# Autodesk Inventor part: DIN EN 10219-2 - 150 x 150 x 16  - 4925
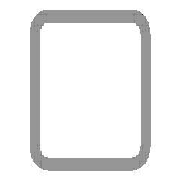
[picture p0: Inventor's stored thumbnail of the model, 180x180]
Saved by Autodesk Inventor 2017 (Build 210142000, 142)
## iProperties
IsCustomPart: 1
Created: 2017-11
Part Number: DIN EN 10219-2 - 150 x 150 x 16  - 4925
Material: Steel, Mild
Description: Cold formed welded structural hollow sections of non-alloy and fine grain structural steel
Document SubType Name: Modeling
Standard: DIN
Designer: iusti
Standard Revision: 2006-07
Standards Organization: DIN
Language: en-US
Size Designation: 150 x 150 x 16
Categories: <MemberInstance><Categories><Category DisplayName="Structural Shapes" InternalName="089c4875-fa83-4c05-b084-43b9cc11f5ed" Mnemonic="GRDR"><CategoryParameter Dis
Stock Number: 150 x 150 x 16
Density: 7.85 g/cm^3
Appearance: Semi-Polished
Mass: 289079 g
Surface Area: 46181.3 cm^2
Volume: 36825.4 cm^3
_CCFamilyMember: 76
_CCFamilyDisplayName: DIN EN 10219-2 (Square Hollow Section - Cold Formed) - Cold formed welded structural hollow sections of non-alloy and fine grain structural steel
_FrameMemberDoc: Frame Member File
_Version: 15.0.0
_GetPNFromCC: 1
G_L: 4925.000 mm
G_W: 150.000 mm
G_H: 150.000 mm
+3C696B27-B370-4381-981B-8782BFEB3638+CUTDETAIL1: Cut
Author: iusti
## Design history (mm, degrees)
node "Start plane"
node "End plane"
sketch "Sketch"
  geometry: L1 (-75, -27)-(-75, 27); L2 (-27, 75)-(27, 75); L3 (75, 27)-(75, -27); L4 (27, -75)-(-27, -75); L5 (-27, 59)-(27, 59); L6 (59, 27)-(59, -27); L7 (27, -59)-(-27, -59); L8 (-59, -27)-(-59, 27); L9 (0, 153.918)-(0, -153.918) reference; L10 (-153.918, 0)-(153.918, 0) reference; A1 r 48 centre (-27, -27) between (-75, -27) and (-27, -75); A2 r 48 centre (-27, 27) between (-27, 75) and (-75, 27); A3 r 48 centre (27, 27) between (75, 27) and (27, 75); A4 r 48 centre (27, -27) between (27, -75) and (75, -27); A5 r 32 centre (-27, 27) between (-27, 59) and (-59, 27); A6 r 32 centre (27, 27) between (59, 27) and (27, 59); A7 r 32 centre (27, -27) between (27, -59) and (59, -27); A8 r 32 centre (-27, -27) between (-59, -27) and (-27, -59)
  constraints: 16 end point, 16 point on circle, 8 centre point, 8 tangent, 4 parallel, 3 equal radius, 2 perpendicular, 7 other
  dimensions: "d7" = 48 radius of A1 (= G_IR); "d10" = 150 distance between parallel lines of L2 L4 (= G_H); "d11" = 150 distance between parallel lines of L1 L3 (= G_W); "d12" = 16 distance between parallel lines of L3 L6 (= G_T); "d15" = 75 distance between parallel lines of L2 L10 (= 0.5 x d10); "d16" = 75 distance between parallel lines of L9 L3 (= 0.5 x d11)
extrude "Body" new body sketch "Sketch" stored distance "d3" = 4925 (= G_L); taper "d4" = 0 deg
node "Driven Length"
  sketch "Sketch3"
    geometry: L1 (0, 0)-(10, 0) reference
    constraints: 2 end point, 1 horizontal
  workplane "Work Plane3"
  sketch "Sketch4"
    geometry: L1 (-2, 75)-(12, 75) reference; L2 (-2, 5000)-(12, 5000) reference
    dimensions: "d18" = 4925 distance between parallel lines of L1 L2 (derived)
workplane "Work Plane4"
split "Split1"
body "Solid1"
other parameters: "G_W" = 150 [user parameter; used in 1 equation term], "G_H" = 150 [user parameter; used in 1 equation term], "G_T" = 16 [user parameter; used in 1 equation term], "G_IR" = 48 [user parameter; used in 1 equation term], "G_L" = 4925 (= d18) [user parameter; used in 1 equation term], "G_OFFSET_START" = -75 [user parameter; used in 1 equation term], "G_OFFSET_END" = 0 [user parameter; used in 1 equation term], "d13" = 75 (= -G_OFFSET_START), "d17" = 90 deg
